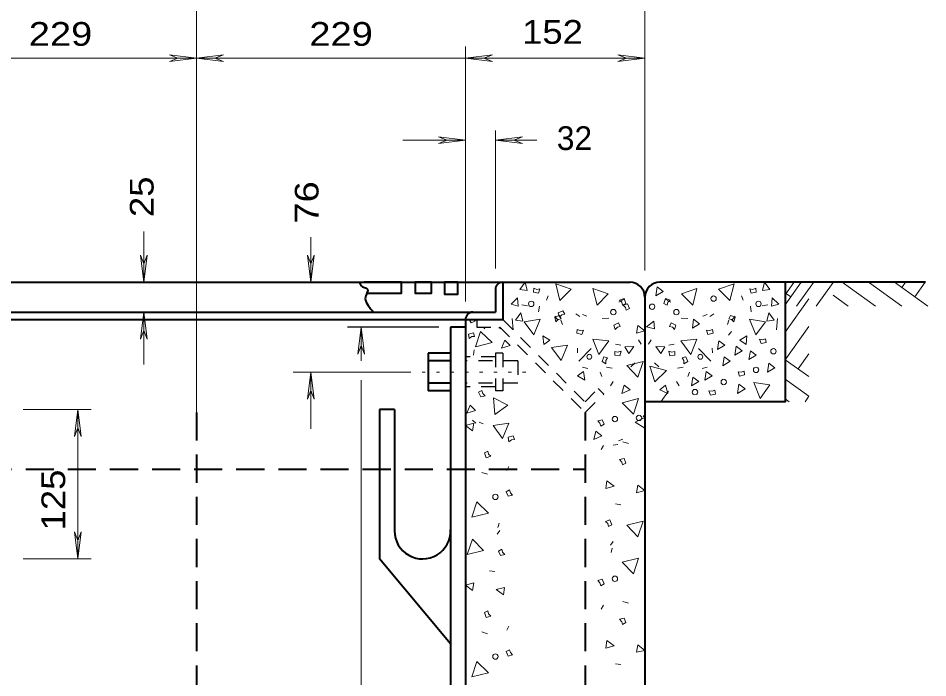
# Model space of a CAD drawing. Extents: x 312583 to 312854, y 144419 to 144597.
# Drawn here: x 312720.66 to 312749.82, y 144459.67 to 144480.8 of the extents above; entities that cross this region are included whole.
import ezdxf

# ---------------------------------------------------------------- set-up
doc = ezdxf.new("R2010")
doc.units = 0
doc.header["$LTSCALE"] = 0.3
for name, pattern in [('DOTTED', [1.5, 0.3, -1.2]), ('MEDIUM_DASHED', [4.5, 3, -1.5]), ('SHORT_DASHED', [2.7, 1.5, -1.2])]:
    doc.linetypes.add(name, pattern=pattern)
doc.layers.add('1', color=7, linetype='Continuous', lineweight=13)

msp = doc.modelspace()

# ---------------------------------------------------------------- linework, layer by layer
at = {"layer": '1'}
for p, q in [((312740.7513, 144472.7252), (312740.7513, 144483.6272)), ((312726.3763, 144468.1712), (312726.3763, 144481.6415)), ((312735.0013, 144471.7285), (312735.0013, 144479.8935)), ((312717.7513, 144479.5179), (312726.3763, 144479.5179)), ((312725.5099, 144479.6252), (312725.7859, 144479.5179)), ((312726.3763, 144479.5179), (312725.5099, 144479.6252)), ((312725.5099, 144479.4105), (312725.7859, 144479.5179)), ((312726.3763, 144479.5179), (312725.5099, 144479.4105)), ((312726.3763, 144479.5179), (312727.2426, 144479.6252)), ((312726.3763, 144479.5179), (312735.0013, 144479.5179)), ((312726.3763, 144479.5179), (312727.2426, 144479.4105)), ((312727.2426, 144479.6252), (312726.9666, 144479.5179)), ((312727.2426, 144479.4105), (312726.9666, 144479.5179)), ((312735.0013, 144479.5179), (312735.8676, 144479.6252)), ((312735.0013, 144479.5179), (312740.7513, 144479.5179)), ((312735.0013, 144479.5179), (312735.8676, 144479.4105)), ((312735.8676, 144479.6252), (312735.5916, 144479.5179)), ((312735.8676, 144479.4105), (312735.5916, 144479.5179)), ((312739.8849, 144479.6252), (312740.1609, 144479.5179)), ((312740.7513, 144479.5179), (312739.8849, 144479.6252)), ((312739.8849, 144479.4105), (312740.1609, 144479.5179)), ((312740.7513, 144479.5179), (312739.8849, 144479.4105)), ((312735.9596, 144472.7865), (312735.9596, 144477.2025)), ((312732.9926, 144476.8959), (312735.0013, 144476.8959)), ((312734.1349, 144477.0032), (312734.4109, 144476.8959)), ((312735.0013, 144476.8959), (312734.1349, 144477.0032)), ((312734.1349, 144476.7885), (312734.4109, 144476.8959)), ((312735.0013, 144476.8959), (312734.1349, 144476.7885)), ((312735.9596, 144476.8959), (312736.8259, 144477.0032)), ((312735.9596, 144476.8959), (312737.2936, 144476.8959)), ((312735.9596, 144476.8959), (312736.8259, 144476.7885)), ((312736.8259, 144477.0032), (312736.5499, 144476.8959)), ((312736.8259, 144476.7885), (312736.5499, 144476.8959)), ((312724.6896, 144472.3419), (312724.6896, 144473.9672)), ((312730.0409, 144472.3419), (312730.0409, 144473.7832)), ((312724.5823, 144473.2082), (312724.6896, 144472.9322)), ((312724.6896, 144472.3419), (312724.5823, 144473.2082)), ((312724.7969, 144473.2082), (312724.6896, 144472.9322)), ((312724.6896, 144472.3419), (312724.7969, 144473.2082)), ((312729.9336, 144473.2082), (312730.0409, 144472.9322)), ((312730.0409, 144472.3419), (312729.9336, 144473.2082)), ((312730.1483, 144473.2082), (312730.0409, 144472.9322)), ((312730.0409, 144472.3419), (312730.1483, 144473.2082)), ((312745.7653, 144472.3419), (312745.2516, 144471.6212)), ((312745.5276, 144472.3342), (312745.2516, 144471.9432)), ((312746.1563, 144472.3342), (312745.6119, 144471.5752)), ((312746.7849, 144472.3342), (312746.2406, 144471.5752)), ((312748.1496, 144471.5829), (312747.0763, 144472.3419)), ((312748.9929, 144471.5829), (312747.9503, 144472.3265)), ((312749.8209, 144471.5829), (312748.7553, 144472.3419)), ((312749.1079, 144472.3419), (312748.9853, 144472.1732)), ((312749.7366, 144472.3419), (312749.4069, 144471.8819)), ((312737.6003, 144471.7745), (312737.6539, 144471.9125)), ((312743.9023, 144471.7745), (312743.8486, 144471.9125)), ((312746.0106, 144471.8129), (312745.2516, 144470.7395)), ((312745.2593, 144471.9969), (312745.4279, 144471.8742)), ((312747.2679, 144471.5829), (312746.7849, 144471.9279)), ((312736.8106, 144471.6212), (312736.9946, 144471.5905)), ((312737.3703, 144471.5752), (312737.3473, 144471.3989)), ((312740.0843, 144471.7975), (312739.9156, 144471.7055)), ((312741.4183, 144471.7975), (312741.5869, 144471.7055)), ((312744.1323, 144471.5752), (312744.1553, 144471.3989)), ((312744.6919, 144471.6212), (312744.5079, 144471.5905)), ((312724.6896, 144471.3835), (312724.5823, 144470.5172)), ((312724.6896, 144469.7045), (312724.6896, 144471.3835)), ((312724.6896, 144471.3835), (312724.7969, 144470.5172)), ((312737.9529, 144471.1382), (312737.8609, 144471.2532)), ((312738.5433, 144471.3299), (312738.6659, 144471.2455)), ((312738.7579, 144471.3069), (312738.8959, 144471.2609)), ((312742.7446, 144471.3069), (312742.6066, 144471.2609)), ((312742.9593, 144471.3299), (312742.8366, 144471.2455)), ((312743.5496, 144471.1382), (312743.6416, 144471.2532)), ((312736.1973, 144471.2149), (312736.2049, 144471.2072)), ((312736.5269, 144470.8239), (312736.4963, 144471.1842)), ((312738.1139, 144470.9925), (312738.0603, 144471.1305)), ((312739.5936, 144471.1919), (312739.3789, 144471.1842)), ((312741.9166, 144471.1919), (312742.1236, 144471.1842)), ((312743.3963, 144470.9925), (312743.4423, 144471.1305)), ((312744.9756, 144470.8239), (312745.0063, 144471.1842)), ((312746.0106, 144470.9312), (312745.2516, 144469.8579)), ((312724.5823, 144470.5172), (312724.6896, 144470.7932)), ((312724.7969, 144470.5172), (312724.6896, 144470.7932)), ((312731.6586, 144470.9082), (312731.5513, 144470.0419)), ((312731.6586, 144470.9082), (312731.7659, 144470.0419)), ((312731.6586, 144469.8272), (312731.6586, 144470.9082)), ((312735.5763, 144470.9082), (312735.6223, 144470.8469)), ((312743.4346, 144470.6475), (312743.5266, 144470.7625)), ((312739.9846, 144470.3332), (312739.8083, 144470.3562)), ((312740.6363, 144470.3639), (312740.5519, 144470.4942)), ((312740.8663, 144470.3639), (312740.9506, 144470.4942)), ((312741.5179, 144470.3332), (312741.6943, 144470.3562)), ((312731.5513, 144470.0419), (312731.6586, 144470.3179)), ((312731.7659, 144470.0419), (312731.6586, 144470.3179)), ((312735.2619, 144470.0035), (312735.2773, 144470.1799)), ((312738.5893, 144470.2335), (312738.5893, 144470.0879)), ((312738.6353, 144469.8119), (312739.0339, 144470.2259)), ((312742.8673, 144469.8119), (312742.4686, 144470.2259)), ((312742.9133, 144470.2335), (312742.9209, 144470.0879)), ((312740.2989, 144469.6355), (312740.4369, 144469.7659)), ((312741.2036, 144469.6355), (312741.0656, 144469.7659)), ((312745.2516, 144469.8579), (312746.0106, 144469.3212)), ((312746.0106, 144470.0495), (312745.6656, 144469.5665)), ((312733.1536, 144469.4669), (312729.4813, 144469.4669)), ((312730.0409, 144469.4669), (312729.9336, 144468.6005)), ((312730.0409, 144467.6499), (312730.0409, 144469.4669)), ((312730.0409, 144469.4669), (312730.1483, 144468.6005)), ((312738.7503, 144469.6279), (312738.9189, 144469.5819)), ((312739.3713, 144469.3212), (312739.3176, 144469.4669)), ((312739.5246, 144469.6279), (312739.7086, 144469.5895)), ((312741.9779, 144469.6279), (312741.7939, 144469.5895)), ((312742.1313, 144469.3212), (312742.1849, 144469.4669)), ((312742.7523, 144469.6279), (312742.5836, 144469.5819)), ((312731.6586, 144440.2415), (312731.6586, 144469.2062)), ((312745.2516, 144469.2369), (312746.0106, 144468.6925)), ((312739.7316, 144469.1602), (312739.6549, 144469.0299)), ((312741.7709, 144469.1602), (312741.8553, 144469.0299)), ((312729.9336, 144468.6005), (312730.0409, 144468.8765)), ((312730.1483, 144468.6005), (312730.0409, 144468.8765)), ((312741.5103, 144468.8535), (312741.2649, 144468.5085)), ((312745.2516, 144468.6082), (312745.3819, 144468.5085)), ((312746.0106, 144468.6925), (312745.8879, 144468.5085)), ((312744.2549, 144468.5085), (312744.2396, 144468.5239)), ((312720.8256, 144468.2709), (312723.0029, 144468.2709)), ((312722.5736, 144468.2709), (312722.4663, 144467.4045)), ((312722.5736, 144468.2709), (312722.5736, 144463.4792)), ((312722.5736, 144468.2709), (312722.6809, 144467.4045)), ((312740.7513, 144468.1099), (312740.6976, 144468.0332)), ((312735.2313, 144467.9259), (312735.3386, 144467.8262)), ((312735.4383, 144467.8645), (312735.5686, 144467.8032)), ((312722.4663, 144467.4045), (312722.5736, 144467.6805)), ((312722.6809, 144467.4045), (312722.5736, 144467.6805)), ((312739.7393, 144467.1285), (312739.8849, 144467.1515)), ((312739.9079, 144467.2589), (312740.0459, 144467.3202)), ((312740.2299, 144467.1745), (312740.0459, 144467.2282)), ((312739.4249, 144467.1132), (312739.3559, 144466.9829)), ((312736.3276, 144466.3082), (312736.3966, 144466.4462)), ((312735.5226, 144466.2545), (312735.7066, 144466.1932)), ((312739.9846, 144465.2119), (312739.8083, 144465.2425)), ((312736.0439, 144464.4835), (312736.0823, 144464.6292)), ((312722.4663, 144464.3455), (312722.5736, 144464.0695)), ((312722.5736, 144463.4792), (312722.4663, 144464.3455)), ((312722.6809, 144464.3455), (312722.5736, 144464.0695)), ((312722.5736, 144463.4792), (312722.6809, 144464.3455)), ((312736.0209, 144464.2689), (312736.1053, 144464.3915)), ((312739.7316, 144464.0389), (312739.6549, 144463.9162)), ((312739.7086, 144463.8242), (312739.6703, 144463.6862)), ((312740.7513, 144463.7859), (312740.7436, 144463.7705)), ((312720.8256, 144463.4792), (312723.0029, 144463.4792)), ((312735.7679, 144463.0959), (312735.9443, 144463.0729)), ((312739.4249, 144461.9995), (312739.3559, 144461.8692)), ((312740.2299, 144462.0609), (312740.0459, 144462.1145)), ((312736.3276, 144461.1945), (312736.3966, 144461.3249)), ((312735.5226, 144461.1409), (312735.7066, 144461.0795)), ((312739.9846, 144460.0982), (312739.8083, 144460.1212))]:
    msp.add_line(p, q, dxfattribs=at)
at = {"layer": '1', "lineweight": 40}
for p, q in [((312716.0723, 144472.3419), (312740.2759, 144472.3419)), ((312735.9596, 144472.1042), (312735.9596, 144471.3835)), ((312736.1973, 144472.3419), (312736.1973, 144471.1459)), ((312745.2516, 144472.3419), (312741.2343, 144472.3419)), ((312749.7519, 144472.3419), (312745.2516, 144472.3419)), ((312740.7513, 144471.8665), (312740.7513, 144468.5085)), ((312716.6703, 144471.3835), (312735.9596, 144471.3835)), ((312716.4326, 144471.1459), (312736.1973, 144471.1459)), ((312735.0013, 144471.1459), (312735.0013, 144438.9689)), ((312735.0013, 144470.9082), (312734.5259, 144470.9082)), ((312734.5259, 144470.9082), (312734.5259, 144440.2415)), ((312733.8053, 144470.0725), (312733.8053, 144468.8689)), ((312734.5259, 144470.0725), (312733.8053, 144470.0725)), ((312734.5259, 144469.8272), (312733.8053, 144469.8272)), ((312734.5259, 144469.1142), (312733.8053, 144469.1142)), ((312734.5259, 144468.8689), (312733.8053, 144468.8689)), ((312732.2489, 144468.2709), (312732.2489, 144463.4792)), ((312732.7243, 144468.2709), (312732.2489, 144468.2709)), ((312732.7243, 144468.2709), (312732.7243, 144464.3762)), ((312734.5259, 144460.7652), (312732.2489, 144463.4792))]:
    msp.add_line(p, q, dxfattribs=at)
at = {"layer": '1', "linetype": 'SHORT_DASHED', "lineweight": 25}
for p, q in [((312735.3616, 144471.1459), (312735.3616, 144470.9082)), ((312736.1973, 144471.1459), (312738.8346, 144468.5085)), ((312735.3616, 144470.9082), (312736.0976, 144470.9082)), ((312736.0976, 144470.9082), (312738.8346, 144468.1712)), ((312735.9596, 144470.0725), (312735.9596, 144468.8689)), ((312736.1973, 144470.0725), (312735.9596, 144470.0725)), ((312736.1973, 144470.0725), (312736.1973, 144468.8689)), ((312735.9596, 144469.9499), (312735.0013, 144469.9499)), ((312736.6803, 144469.8272), (312735.0013, 144469.8272)), ((312736.6803, 144469.8272), (312736.6803, 144469.1142)), ((312736.6803, 144469.1142), (312735.0013, 144469.1142)), ((312735.9596, 144468.9915), (312735.0013, 144468.9915)), ((312738.8346, 144468.5085), (312739.2563, 144468.9379)), ((312739.2563, 144468.9379), (312739.4326, 144468.7615)), ((312736.1973, 144468.8689), (312735.9596, 144468.8689)), ((312738.8346, 144468.1712), (312739.4326, 144468.7615))]:
    msp.add_line(p, q, dxfattribs=at)
at = {"layer": '1', "lineweight": 25}
msp.add_line((312734.1503, 144470.9082), (312731.2216, 144470.9082), dxfattribs=at)
at = {"layer": '1', "linetype": 'DOTTED'}
msp.add_line((312733.1536, 144469.4669), (312736.9716, 144469.4669), dxfattribs=at)
at = {"layer": '1', "linetype": 'MEDIUM_DASHED', "lineweight": 40}
for p, q in [((312726.3763, 144468.1712), (312726.3763, 144433.8092)), ((312738.8346, 144468.1712), (312738.8346, 144439.2602)), ((312699.3053, 144466.3542), (312738.8346, 144466.3542))]:
    msp.add_line(p, q, dxfattribs=at)
at = {"layer": '1', "lineweight": 40}
for points in [[(312731.8349, 144471.9969), (312732.9466, 144471.9969), (312732.9466, 144472.3419), (312731.7583, 144472.3419)], [(312745.2516, 144472.3419), (312745.2516, 144468.5085), (312740.7513, 144468.5085)], [(312740.7513, 144468.5085), (312740.7513, 144461.6392), (312740.7513, 144438.9689)]]:
    msp.add_lwpolyline(points, dxfattribs=at)
for points in [[(312733.3913, 144472.3419), (312733.3913, 144471.9969), (312733.9126, 144471.9969), (312733.9126, 144472.3419)], [(312734.3343, 144472.3419), (312734.3343, 144471.9585), (312734.7559, 144471.9585), (312734.7559, 144472.3419)]]:
    msp.add_lwpolyline(points, close=True, dxfattribs=at)
at = {"layer": '1'}
for points in [[(312736.7416, 144472.1119), (312736.9793, 144472.0812), (312736.9179, 144472.3419)], [(312737.2859, 144472.1119), (312737.1939, 144472.1502), (312737.1786, 144472.0275), (312737.3396, 144471.9969), (312737.3856, 144472.1349)], [(312738.0296, 144471.7592), (312738.3899, 144472.1272), (312737.8993, 144472.2882)], [(312739.2179, 144471.6135), (312739.5783, 144471.9739), (312739.0876, 144472.1425)], [(312741.1499, 144472.1962), (312741.3416, 144472.0505), (312741.1039, 144471.9125)], [(312742.2846, 144471.6135), (312741.9243, 144471.9739), (312742.4149, 144472.1425)], [(312743.4729, 144471.7592), (312743.1126, 144472.1272), (312743.6109, 144472.2882)], [(312744.2166, 144472.1119), (312744.3086, 144472.1502), (312744.3239, 144472.0275), (312744.1629, 144471.9969), (312744.1169, 144472.1349)], [(312744.7609, 144472.1119), (312744.5233, 144472.0812), (312744.5846, 144472.3419)], [(312736.4656, 144471.6442), (312736.6956, 144471.5752), (312736.6726, 144471.8435)], [(312740.0153, 144471.7055), (312740.0383, 144471.6135), (312740.1456, 144471.6672), (312740.0843, 144471.8205), (312739.9386, 144471.7745)], [(312741.4873, 144471.7055), (312741.4643, 144471.6135), (312741.3569, 144471.6672), (312741.4183, 144471.8205), (312741.5639, 144471.7745)], [(312745.0446, 144471.6442), (312744.8069, 144471.5752), (312744.8299, 144471.8435)], [(312740.1303, 144471.5369), (312740.1533, 144471.4449), (312740.2606, 144471.4985), (312740.1993, 144471.6519), (312740.0536, 144471.6059)], [(312736.6036, 144471.1305), (312736.8413, 144471.0999), (312736.7723, 144471.3605)], [(312737.9759, 144471.1535), (312738.0679, 144471.1765), (312738.0066, 144471.2839), (312737.8609, 144471.2225), (312737.8993, 144471.0769)], [(312738.0909, 144471.2992), (312738.1829, 144471.3222), (312738.1216, 144471.4295), (312737.9759, 144471.3605), (312738.0143, 144471.2225)], [(312743.5266, 144471.1535), (312743.4423, 144471.1765), (312743.4959, 144471.2839), (312743.6493, 144471.2225), (312743.6033, 144471.0769)], [(312744.8989, 144471.1305), (312744.6613, 144471.0999), (312744.7303, 144471.3605)], [(312737.4009, 144471.1612), (312736.8873, 144471.0769), (312737.1939, 144470.6552)], [(312739.8696, 144470.9082), (312739.9616, 144470.9312), (312739.9079, 144471.0385), (312739.7546, 144470.9695), (312739.8006, 144470.8315)], [(312740.5213, 144470.9619), (312740.4829, 144470.7165), (312740.7513, 144470.7855)], [(312741.0349, 144471.0922), (312741.0656, 144470.8469), (312740.8049, 144470.9159)], [(312741.6329, 144470.9082), (312741.5409, 144470.9312), (312741.5946, 144471.0385), (312741.7479, 144470.9695), (312741.7019, 144470.8315)], [(312742.3153, 144471.1612), (312742.5069, 144471.0155), (312742.2769, 144470.8775)], [(312744.1016, 144471.1612), (312744.6153, 144471.0769), (312744.3086, 144470.6552)], [(312735.2006, 144470.6015), (312735.2926, 144470.6092), (312735.2543, 144470.7242), (312735.0933, 144470.6859), (312735.1163, 144470.5402)], [(312735.8523, 144470.4099), (312735.4843, 144470.7702), (312735.3233, 144470.2719)], [(312738.6736, 144470.7932), (312738.5816, 144470.8315), (312738.5663, 144470.7089), (312738.7273, 144470.6705), (312738.7809, 144470.8085)], [(312742.8289, 144470.7932), (312742.9209, 144470.8315), (312742.9363, 144470.7089), (312742.7753, 144470.6705), (312742.7293, 144470.8085)], [(312736.4349, 144470.3179), (312736.2586, 144470.4865), (312736.1589, 144470.2335)], [(312737.5083, 144470.3485), (312737.7076, 144470.4865), (312737.4776, 144470.6322)], [(312739.6013, 144470.4712), (312739.0876, 144470.5249), (312739.2793, 144470.0342)], [(312741.9013, 144470.4712), (312742.4149, 144470.5249), (312742.2233, 144470.0342)], [(312743.1203, 144470.4712), (312743.3119, 144470.3255), (312743.0819, 144470.1875)], [(312743.9943, 144470.3485), (312743.7949, 144470.4865), (312744.0249, 144470.6322)], [(312744.5309, 144470.4942), (312744.6153, 144470.5325), (312744.6383, 144470.4099), (312744.4773, 144470.3792), (312744.4236, 144470.5172)], [(312738.2749, 144470.3332), (312737.7613, 144470.2565), (312738.0679, 144469.8349)], [(312739.8849, 144470.1032), (312739.7929, 144470.1262), (312739.7929, 144470.0035), (312739.9539, 144469.9882), (312739.9923, 144470.1339)], [(312740.1073, 144470.2719), (312740.2376, 144470.0649), (312740.3986, 144470.2872)], [(312741.3953, 144470.2719), (312741.2649, 144470.0649), (312741.1039, 144470.2872)], [(312741.6176, 144470.1032), (312741.7096, 144470.1262), (312741.7096, 144470.0035), (312741.5486, 144469.9882), (312741.5179, 144470.1339)], [(312743.6799, 144470.2949), (312743.8716, 144470.1492), (312743.6339, 144470.0035)], [(312744.1323, 144470.1492), (312744.3239, 144470.0035), (312744.0863, 144469.8655)], [(312739.5016, 144469.8349), (312739.5553, 144469.9192), (312739.4403, 144469.9575), (312739.3789, 144469.8042), (312739.5016, 144469.7275)], [(312740.1686, 144469.6739), (312740.5289, 144469.3059), (312740.6976, 144469.8042)], [(312742.0009, 144469.8349), (312741.9473, 144469.9192), (312742.0623, 144469.9575), (312742.1236, 144469.8042), (312742.0009, 144469.7275)], [(312743.2889, 144469.9575), (312743.4806, 144469.8119), (312743.2506, 144469.6662)], [(312738.7886, 144469.4899), (312738.5969, 144469.3442), (312738.8269, 144469.2062)], [(312741.4413, 144469.5205), (312741.0733, 144469.1525), (312740.9123, 144469.6509)], [(312742.7139, 144469.4899), (312742.9133, 144469.3442), (312742.6756, 144469.2062)], [(312743.8409, 144469.4592), (312743.9329, 144469.4975), (312743.9483, 144469.3749), (312743.7873, 144469.3365), (312743.7413, 144469.4745)], [(312744.7303, 144469.7505), (312744.9219, 144469.6049), (312744.6843, 144469.4592)], [(312742.2923, 144469.3059), (312742.4839, 144469.1602), (312742.2463, 144469.0222)], [(312740.2836, 144468.8995), (312740.0843, 144469.0452), (312740.0153, 144468.7769)], [(312741.2266, 144468.8995), (312741.4183, 144469.0452), (312741.4873, 144468.7769)], [(312742.9056, 144468.8535), (312742.9976, 144468.8842), (312743.0129, 144468.7615), (312742.8519, 144468.7309), (312742.8059, 144468.8689)], [(312743.7643, 144469.0759), (312743.9636, 144468.9302), (312743.7259, 144468.7845)], [(312744.2396, 144469.1295), (312744.7533, 144469.0529), (312744.4466, 144468.6235)], [(312735.5533, 144468.7845), (312735.5303, 144468.8765), (312735.4229, 144468.8229), (312735.4919, 144468.6695), (312735.6299, 144468.7079)], [(312735.9443, 144468.1022), (312736.3583, 144468.4012), (312735.8983, 144468.6389)], [(312740.0229, 144468.4855), (312740.3833, 144468.1175), (312740.5519, 144468.6159)], [(312735.3233, 144468.2325), (312735.1469, 144468.4012), (312735.0473, 144468.1482)], [(312735.2313, 144467.5809), (312735.2696, 144467.8262), (312735.0013, 144467.7572)], [(312736.3966, 144467.8339), (312735.8906, 144467.7572), (312736.1896, 144467.3355)], [(312739.3099, 144467.8262), (312739.3406, 144467.7342), (312739.4479, 144467.7955), (312739.3789, 144467.9412), (312739.2409, 144467.9029)], [(312739.3713, 144467.4275), (312739.1796, 144467.5732), (312739.1106, 144467.3049)], [(312736.4809, 144467.2972), (312736.5729, 144467.3049), (312736.5346, 144467.4199), (312736.3736, 144467.3815), (312736.3889, 144467.2359)], [(312735.7373, 144466.8372), (312735.7143, 144466.9292), (312735.6069, 144466.8755), (312735.6683, 144466.7222), (312735.8139, 144466.7682)], [(312740.0153, 144466.5842), (312740.0383, 144466.4999), (312740.1456, 144466.5535), (312740.0843, 144466.6992), (312739.9386, 144466.6609)], [(312739.5323, 144465.9862), (312739.5016, 144465.7409), (312739.7699, 144465.8099)], [(312736.4426, 144465.6029), (312736.4119, 144465.6949), (312736.3046, 144465.6335), (312736.3736, 144465.4879), (312736.5116, 144465.5262)], [(312740.5213, 144465.8405), (312740.4829, 144465.6029), (312740.7513, 144465.6719)], [(312735.7373, 144464.9435), (312735.3693, 144465.3115), (312735.2083, 144464.8132)], [(312739.5629, 144464.6139), (312739.5859, 144464.5219), (312739.6933, 144464.5755), (312739.6243, 144464.7289), (312739.4863, 144464.6829)], [(312740.1686, 144464.5602), (312740.5289, 144464.1922), (312740.6976, 144464.6905)], [(312735.5839, 144463.7552), (312735.2236, 144464.1155), (312735.0549, 144463.6249)], [(312736.1896, 144463.7015), (312736.1666, 144463.7935), (312736.0593, 144463.7322), (312736.1283, 144463.5865), (312736.2663, 144463.6249)], [(312740.0229, 144463.3719), (312740.3833, 144463.0039), (312740.5519, 144463.5022)], [(312739.3099, 144462.7125), (312739.3406, 144462.6205), (312739.4479, 144462.6819), (312739.3789, 144462.8275), (312739.2409, 144462.7892)], [(312735.2313, 144462.4672), (312735.2696, 144462.7125), (312735.0013, 144462.6435)], [(312736.2203, 144462.3292), (312736.2509, 144462.5669), (312735.9826, 144462.5055)], [(312735.7373, 144461.7235), (312735.7143, 144461.8155), (312735.6069, 144461.7619), (312735.6683, 144461.6085), (312735.8139, 144461.6469)], [(312740.0153, 144461.4705), (312740.0383, 144461.3785), (312740.1456, 144461.4399), (312740.0843, 144461.5855), (312739.9386, 144461.5472)], [(312739.5323, 144460.8649), (312739.5016, 144460.6272), (312739.7699, 144460.6962)], [(312740.5213, 144460.7269), (312740.4829, 144460.4892), (312740.7513, 144460.5505)], [(312736.4426, 144460.4815), (312736.4119, 144460.5735), (312736.3046, 144460.5199), (312736.3736, 144460.3665), (312736.5116, 144460.4125)], [(312735.7373, 144459.8299), (312735.3693, 144460.1902), (312735.2083, 144459.6995)]]:
    msp.add_lwpolyline(points, close=True, dxfattribs=at)
for points in [[(312735.1163, 144471.1459), (312735.1853, 144471.0385), (312735.3156, 144471.0922), (312735.2466, 144471.1459)], [(312736.1053, 144470.9005), (312736.0746, 144470.8852), (312736.1743, 144470.8315)], [(312740.7513, 144468.0102), (312740.4446, 144467.8569), (312740.7513, 144467.6729)]]:
    msp.add_lwpolyline(points, dxfattribs=at)
for centre, radius in [((312742.9547, 144471.8194), 0.0865), ((312737.1084, 144471.6508), 0.0865), ((312740.9834, 144471.5597), 0.0865), ((312744.3941, 144471.6508), 0.0865), ((312739.7405, 144471.386), 0.0865), ((312741.7621, 144471.386), 0.0865), ((312744.8742, 144470.1328), 0.0865), ((312738.9728, 144469.9566), 0.0784), ((312742.5297, 144469.9566), 0.0784), ((312744.3165, 144469.5367), 0.0865), ((312743.2786, 144469.1476), 0.0865), ((312742.3576, 144468.8237), 0.0865), ((312739.7916, 144467.9602), 0.0865), ((312740.5628, 144467.9971), 0.0865), ((312735.9609, 144465.469), 0.0865), ((312739.7916, 144462.8446), 0.0865), ((312735.9609, 144460.3534), 0.0865)]:
    msp.add_circle(centre, radius, dxfattribs=at)
at = {"layer": '1', "lineweight": 40}
for centre, radius, start, end in [((312736.1992, 144472.1061), 0.2396, 90, 180), ((312740.2721, 144471.8665), 0.4792, 0, 90), ((312741.2304, 144471.8665), 0.4792, 90, 180), ((312735.2409, 144471.1478), 0.2396, 90, 180), ((312733.6241, 144464.3796), 0.8984, 180.03057, 1.87136)]:
    msp.add_arc(centre, radius, start, end, dxfattribs=at)
msp.add_spline([(312731.6126, 144472.3419), (312731.6509, 144472.2345), (312731.8656, 144472.1195), (312731.8043, 144471.9049), (312731.7889, 144471.8282), (312731.8809, 144471.5982), (312732.0573, 144471.3835)], degree=3, dxfattribs=at)

# ---------------------------------------------------------------- texts
at = {"layer": '1'}
for s, width, p in [('229 ', 1.2, (312721.0039, 144479.9187)), ('229 ', 1.2, (312729.9972, 144479.9187)), ('152 ', 1.15, (312736.8156, 144479.9823))]:
    msp.add_text(s, height=0.76, dxfattribs=dict(at, width=width)).set_placement(p)
msp.add_text('32', height=0.76, dxfattribs=at).set_placement((312737.93, 144476.5803))
for s, width, p in [('25 ', 1.15, (312725.004, 144474.43)), ('76 ', 1.2, (312730.2916, 144474.2221)), ('125 ', 1.15, (312722.1709, 144464.3926))]:
    msp.add_text(s, height=0.76, rotation=90, dxfattribs=dict(at, width=width)).set_placement(p)

doc.saveas('drawing.dxf')
